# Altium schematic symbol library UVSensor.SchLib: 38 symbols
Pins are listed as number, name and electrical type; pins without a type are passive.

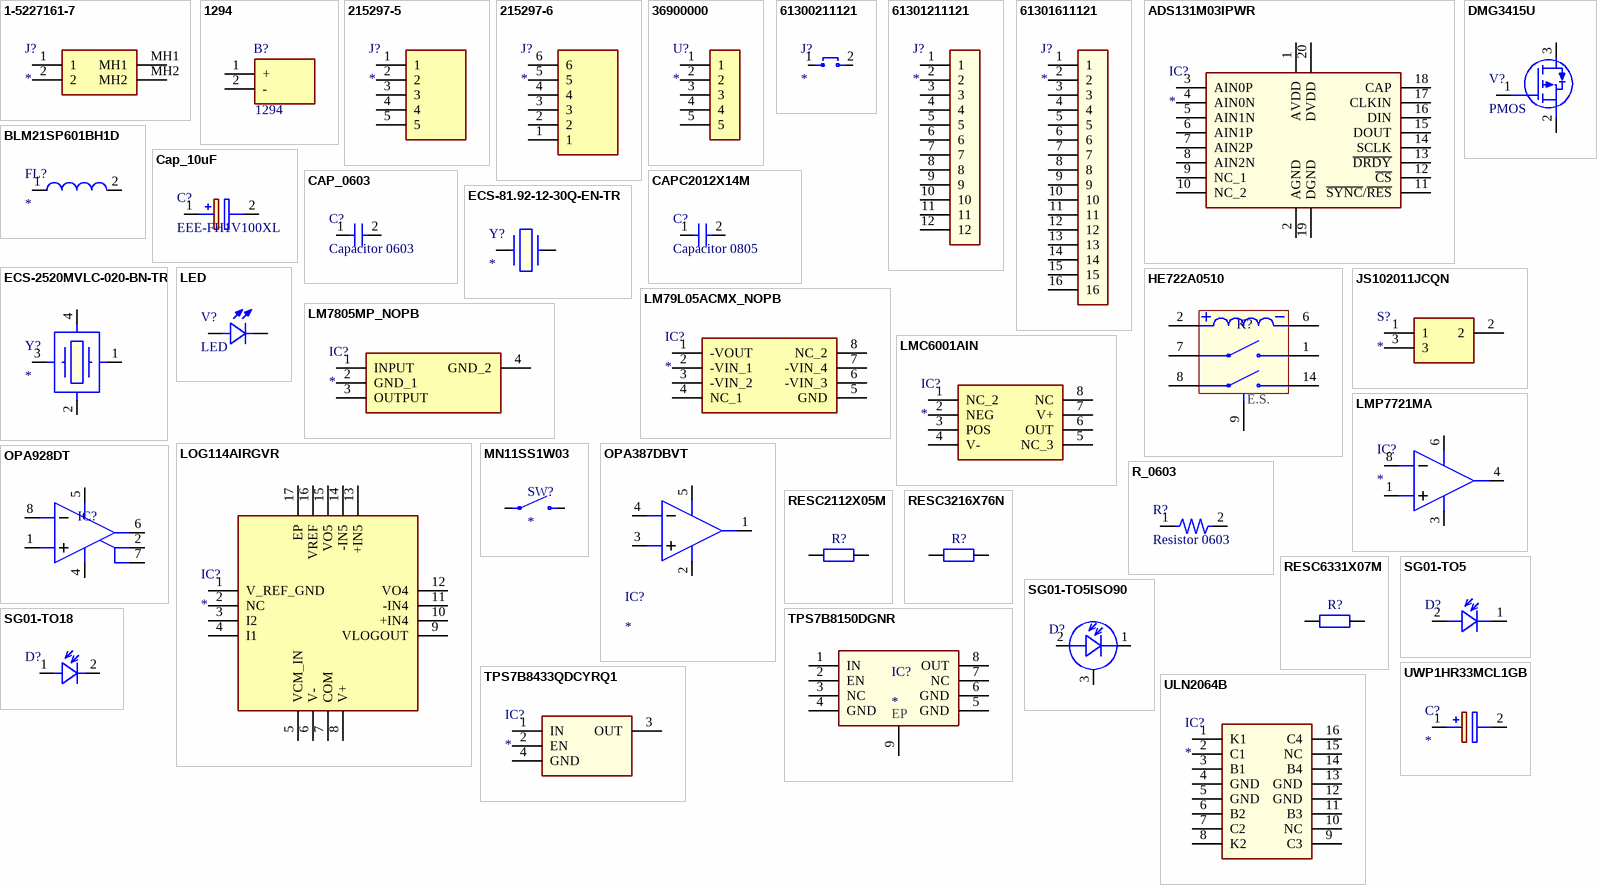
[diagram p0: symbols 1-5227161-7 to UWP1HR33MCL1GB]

## 1-5227161-7
designator J?
Connector; Manufacturer_Name: TE Connectivity; Manufacturer_Part_Number: 1-5227161-7
footprint 152271617
pins: 1, 2, MH1, MH2

## 1294
designator B?
KEYSTONE - 1294 - Battery Holder, PP3 (9V) x 1, Through Hole; Manufacturer_Name: Keystone Electronics; Geometry.Height: 20.57mm
footprint 1294
pins: 1 +, 2 -

## 215297-5
designator J?
Connector; Manufacturer_Name: TE Connectivity; Manufacturer_Part_Number: 215297-5
footprint RHDR5W78P0X254_1X5_1280X252X700P
pins: 1, 2, 3, 4, 5

## 215297-6
designator J?
Connector; Manufacturer_Name: TE Connectivity; Manufacturer_Part_Number: 215297-6
footprint 2152976
pins: 1, 2, 3, 4, 5, 6

## 36900000
designator U?
Undefined or Miscellaneous; Manufacturer_Name: Wurth Elektronik; Manufacturer_Part_Number: 36900000
footprint 36900000
pins: 1, 2, 3, 4, 5

## 61300211121
designator J?
Connector; Manufacturer_Name: Wurth Elektronik; Manufacturer_Part_Number: 61300211121
footprint HDRV2W110P0X254_1X2_508X254X854P
pins: 1, 2

## 61301211121
designator J?
Connector; Manufacturer_Name: Wurth Elektronik; Manufacturer_Part_Number: 61301211121
footprint HDRV12W79P0X254_1X12_3048X254X874P
pins: 1, 2, 3, 4, 5, 6, 7, 8, 9, 10, 11, 12

## 61301611121
designator J?
Connector; Manufacturer_Name: Wurth Elektronik; Manufacturer_Part_Number: 61301611121
footprint HDRV16W79P0X254_1X16_4064X254X874P
pins: 1, 2, 3, 4, 5, 6, 7, 8, 9, 10, 11, 12, 13, 14, 15, 16

## ADS131M03IPWR
designator IC?
Integrated Circuit; Manufacturer_Name: Texas Instruments; Manufacturer_Part_Number: ADS131M03IPWR
footprint SOP65P640X120-20N
pins: 1 AVDD, 2 AGND, 3 AIN0P, 4 AIN0N, 5 AIN1N, 6 AIN1P, 7 AIN2P, 8 AIN2N, 9 NC_1, 10 NC_2, 11 ~{SYNC}/~{RES}, 12 ~{CS}, 13 ~{DRDY}, 14 SCLK, 15 DOUT, 16 DIN, 17 CLKIN, 18 CAP, 19 DGND, 20 DVDD

## BLM21SP601BH1D
designator FL?
Filter; Manufacturer_Name: Murata Electronics; Manufacturer_Part_Number: BLM21SP601BH1D
footprint BLM21AG102BH1J
pins: 1, 2

## Cap_10uF
designator C?, comment EEE-FH1V100XL
Capacitor Polarised; Manufacturer_Name: Panasonic
footprint EEEHP1H4R7P
pins: 1 +, 2 -

## CAP_0603
designator C?, comment Capacitor 0603
footprint C_0603
pins: 1, 2

## CAPC2012X14M
designator C?, comment Capacitor 0805
footprint CAPC2012X14M (Capacitor, 0805 (2012 metric), 2.0x1.25x1.4mm, Kemet)
pins: 1, 2

## DMG3415U
designator V?, comment PMOS
MOSFETs MOSFET BVDSS: 8V~24V SOT23 T&R 3K
footprint DMG3415U
pins: 1, 2, 3

## ECS-81.92-12-30Q-EN-TR
designator Y?
Crystal or Oscillator; Manufacturer_Name: ECS; Manufacturer_Part_Number: ECS-81.92-12-30Q-EN-TR
footprint ECS81921230QENTR
pins: 2 OUT/IN, ?1

## ECS-2520MVLC-020-BN-TR
designator Y?
Crystal or Oscillator; Manufacturer_Name: ECS; Manufacturer_Part_Number: ECS-2520MVLC-020-BN-TR
footprint ECS2520MVLC020BNTR
pins: 1 TRI-STATE, 2 GND, 3 OUTPUT, 4 VDD

## HE722A0510
designator K?  (value not drawn)
2 Form A (DPST-NO) Reed Relay, Littelfuse
footprint HE722A0510
pins: 1 NO_1, 2 +COIL, 6 -COIL, 7 COM_1, 8 COM_2, 9 E.S, 14 NO_2

## JS102011JCQN
designator S?
Switch; Manufacturer_Name: C & K COMPONENTS; Manufacturer_Part_Number: JS102011JCQN
footprint JS102011JCQN
pins: 1, 2, 3

## LED
designator V?
LED, 2 pin
footprint LEDC2012X85N
pins: 1, 2

## LM79L05ACMX_NOPB
designator IC?
Integrated Circuit; Manufacturer_Name: Texas Instruments; Manufacturer_Part_Number: LM79L05ACMX/NOPB
footprint SOIC127P600X175-8N
pins: 1 -VOUT, 2 -VIN_1, 3 -VIN_2, 4 NC_1, 5 GND, 6 -VIN_3, 7 -VIN_4, 8 NC_2

## LM7805MP_NOPB
designator IC?
Integrated Circuit; Manufacturer_Name: Texas Instruments; Manufacturer_Part_Number: LM7805MP/NOPB
footprint SOT230P700X180-4N
pins: 1 INPUT, 2 GND_1, 3 OUTPUT, 4 GND_2

## LMC6001AIN
designator IC?
Integrated Circuit; Manufacturer_Name: Texas Instruments; Manufacturer_Part_Number: LMC6001AIN
footprint LMC6001AIN
pins: 1 NC_2, 2 NEG, 3 POS, 4 V-, 5 NC_3, 6 OUT, 7 V+, 8 NC

## LMP7721MA
designator IC?
Integrated Circuit; Manufacturer_Name: Texas Instruments; Manufacturer_Part_Number: LMP7721MA
footprint SOIC127P600X175-8N
pins: 1 IN+, 3 V-, 4 VOUT, 6 V+, 8 IN-

## LOG114AIRGVR
designator IC?
Integrated Circuit; Manufacturer_Name: Texas Instruments; Manufacturer_Part_Number: LOG114AIRGVR
footprint QFN65P400X400X100-17N-D
pins: 1 V_REF_GND, 2 NC, 3 I2, 4 I1, 5 VCM_IN, 6 V-, 7 COM, 8 V+, 9 VLOGOUT, 10 +IN4, 11 -IN4, 12 VO4, 13 +IN5, 14 -IN5, 15 VO5, 16 VREF, 17 EP

## MN11SS1W03
designator SW?
SPST Toggle Switch
footprint M2011SS1W03
pins: 2, 3

## OPA387DBVT
designator IC?
Integrated Circuit; Manufacturer_Name: Texas Instruments; Manufacturer_Part_Number: OPA387DBVT
footprint SOT95P280X145-5N
pins: 1 OUT, 2 V-, 3 +IN, 4 -IN, 5 V+

## OPA928DT
designator IC?
Precision Amplifier, femptoampere-input-bias, Texas Instruments
footprint OPA928DT (SOIC, 8-Leads, Body 4,91x3,90mm, Pitch 1,27mm, IPC Medium Density)
pins: 1, 2, 4, 5 V+, 6, 7, 8

## R_0603
designator R?, comment Resistor 0603
footprint R_0603
pins: 1, 2

## RESC2112X05M
designator R?
0805 Resistor
footprint RESC2112X05M (Resistor, 0805 (2012 metric), 2.05x1.25x0.5mm, Vishay)
pins: 1, 2

## RESC3216X76N
designator R?
1206 Resistor
footprint RESC3216X76N
pins: 1, 2

## RESC6331X07M
designator R?
2512 Resistor
footprint RESC6331X07M (Resistor, 2512 (6332 metric), 6.3x3.2x0.7mm, Vishay)
pins: 1, 2

## SG01-TO5
designator D?, comment Photodiode A=0.06mm2  (value not drawn)
SG01 series photodiode, TO-5 housing
footprint TO254P939X470-2P
pins: 1 A, 2 C

## SG01-TO5ISO90
designator D?, comment Photodiode A=0.06mm2  (value not drawn)
SG01 series photodiode, TO-5 housing
footprint TO254P939X470-3P
pins: 1 A, 2 C, 3

## SG01-TO18
designator D?, comment Photodiode A=0.06mm2  (value not drawn)
SG01 series photodiode, TO18 housing
footprint TO18
pins: 1 A, 2 C

## TPS7B8150DGNR
designator IC?
Integrated Circuit; Manufacturer_Name: Texas Instruments; Manufacturer_Part_Number: TPS7B8150DGNR
footprint SOP65P490X110-9N
pins: 1 IN, 2 EN, 3 NC, 4 GND, 5 GND, 6 GND, 7 NC, 8 OUT, 9 EP

## TPS7B8433QDCYRQ1
designator IC?
Integrated Circuit; Manufacturer_Name: Texas Instruments; Manufacturer_Part_Number: TPS7B8433QDCYRQ1
footprint SOT230P700X180-4N - duplicate
pins: 1 IN, 2 EN, 3 OUT, 4 GND

## ULN2064B
designator IC?
Integrated Circuit; Manufacturer_Name: STMicroelectronics; Manufacturer_Part_Number: ULN2064B
footprint DIP880W50P254L2000H510Q16N
pins: 1 K1, 2 C1, 3 B1, 4 GND, 5 GND, 6 B2, 7 C2, 8 K2, 9 C3, 10 NC, 11 B3, 12 GND, 13 GND, 14 B4, 15 NC, 16 C4

## UWP1HR33MCL1GB
designator C?
Capacitor Polarised; Manufacturer_Name: Nichicon; Manufacturer_Part_Number: UWP1HR33MCL1GB
footprint CAPAE430X550N
pins: 1 +, 2 -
